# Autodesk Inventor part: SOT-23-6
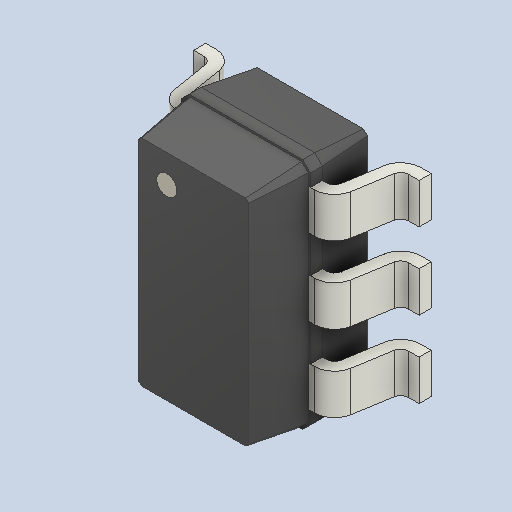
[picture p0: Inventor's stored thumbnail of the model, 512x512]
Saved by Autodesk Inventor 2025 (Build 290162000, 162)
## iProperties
Created: 2026-09
Part Number: SOT-23-6
Material: Generic
Document SubType Name: Modeling
Designer: Leonardo
Density: 1 g/cm^3
Appearance: Default
Author: Leonardo
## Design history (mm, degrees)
feature "Base1"
body "Solid1"
